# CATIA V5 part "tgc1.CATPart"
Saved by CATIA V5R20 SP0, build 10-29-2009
Part number: TGC1
Revision: 4
Definition: design
Nomenclature: TGC1
Source: made
Description: NOT SPECIFIED
Bounding box of the stored display mesh (mm): x -2 to 16, y -4 to 4, z -20 to 2
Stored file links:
  C:\Users\Utente\Desktop\IO LAVORO\3D X SITO CF\X SITO\PLASTICA\TGC-XS\tgc1.CATPart
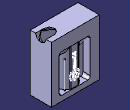
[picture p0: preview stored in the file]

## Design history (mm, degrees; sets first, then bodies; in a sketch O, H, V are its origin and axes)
Set1
  Line1 "LINE #4883": stored without definition
  DatumCurve1 "COMPOSITE_CURVE #4971"
  DatumCurve2 "COMPOSITE_CURVE #5025"
  DatumCurve3 "COMPOSITE_CURVE #5052"
  DatumCurve4 "COMPOSITE_CURVE #5077"
  DatumCurve5 "COMPOSITE_CURVE #5104"
  DatumCurve6 "COMPOSITE_CURVE #5130"
  DatumCurve7 "COMPOSITE_CURVE #5294"
  DatumCurve8 "COMPOSITE_CURVE #5319"
  DatumCurve9 "COMPOSITE_CURVE #5380"
  DatumCurve10 "COMPOSITE_CURVE #5497"
  DatumSurface1 "OPEN_SHELL #4723"
  DatumSurface2 "OPEN_SHELL #4776"
  DatumSurface3 "OPEN_SHELL #4873"
Body1 "MANIFOLD_SOLID_BREP #4874" (main body)
  Solid1: solid without history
